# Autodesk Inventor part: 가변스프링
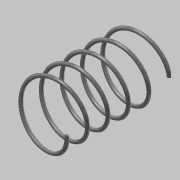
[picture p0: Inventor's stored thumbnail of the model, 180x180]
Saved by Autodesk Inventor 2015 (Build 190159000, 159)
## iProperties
Created: 2023-04
Part Number: 가변스프링
Material: 스테인레스 스틸
Document SubType Name: Modeling
Designer: SCD-A08
Density: 8 g/cm^3
Appearance: 반연마
Mass: 12.5397 g
Surface Area: 31.641 cm^2
Volume: 1.56746 cm^3
Author: SCD-A08
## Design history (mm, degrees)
sketch "스케치4"
  geometry: L1 (0, 0)-(16, 0); L2 (16, 0)-(16, -46.5); L3 (16, -46.5)-(0, -46.5); L4 (0, -46.5)-(0, 0); C1 r 1 at (16, 0)
  constraints: 8 end point, 2 parallel, 1 centre point, 1 coincident, 1 horizontal, 1 perpendicular
  dimensions: "d15" = 46.5 distance of L1.end L2.end (derived); "d16" = 32 diameter of L2 L4; "d17" = 2 diameter of C1
feature "코일2" sketch "스케치4" pitch "d18" = 10; turns "d20" = 5; dims "d19" = 46.5 (= d15), "d21" = 0, angle "d22" = 90 deg, angle "d23" = 90 deg, "d24" = 0, "d25" = 0
node "작업 평면3"
node "작업 평면4"
sketch "스케치5"
  geometry: L1 (-15, 0)-(-17, 0) reference; 1 further point
  constraints: 1 horizontal alignment
extrude "돌출3" cut sketch "스케치5" distance "d26" = 10; taper "d27" = 0 deg
sketch "스케치6"
  geometry: L1 (-17, 0)-(-15, 0) reference; 1 further point
  constraints: 1 horizontal alignment
extrude "돌출4" cut sketch "스케치6" distance "d28" = 10; taper "d29" = 0 deg
node "솔리드2"
node "절단 모서리 투영3"
node "절단 모서리 투영4"
